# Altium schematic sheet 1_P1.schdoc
size 429 x 307 mm; Symbol: Drawing-Symbol_A4; Device: Drawing-Symbol_A4; Company: 嘉立创EDA; Version: V1.0; Page Size: A4; @Project Name: Dual_Motor_Driver_V3.1; @Page Count: 1; @Update Date: 2025-08-31; @Create Date: 2025-08-30; @Schematic Name: Schematic1; @Page No: 1; @Page Name: P1; @Create Time: 14:29:45; @Update Time: 22:24:23; Width: 1655; Height: 1170; Region Start: 1; X Region Count: 6; Y Region Count: 4; Blade Width: 10; Title Block Position: 3; @Board Name: PCB2
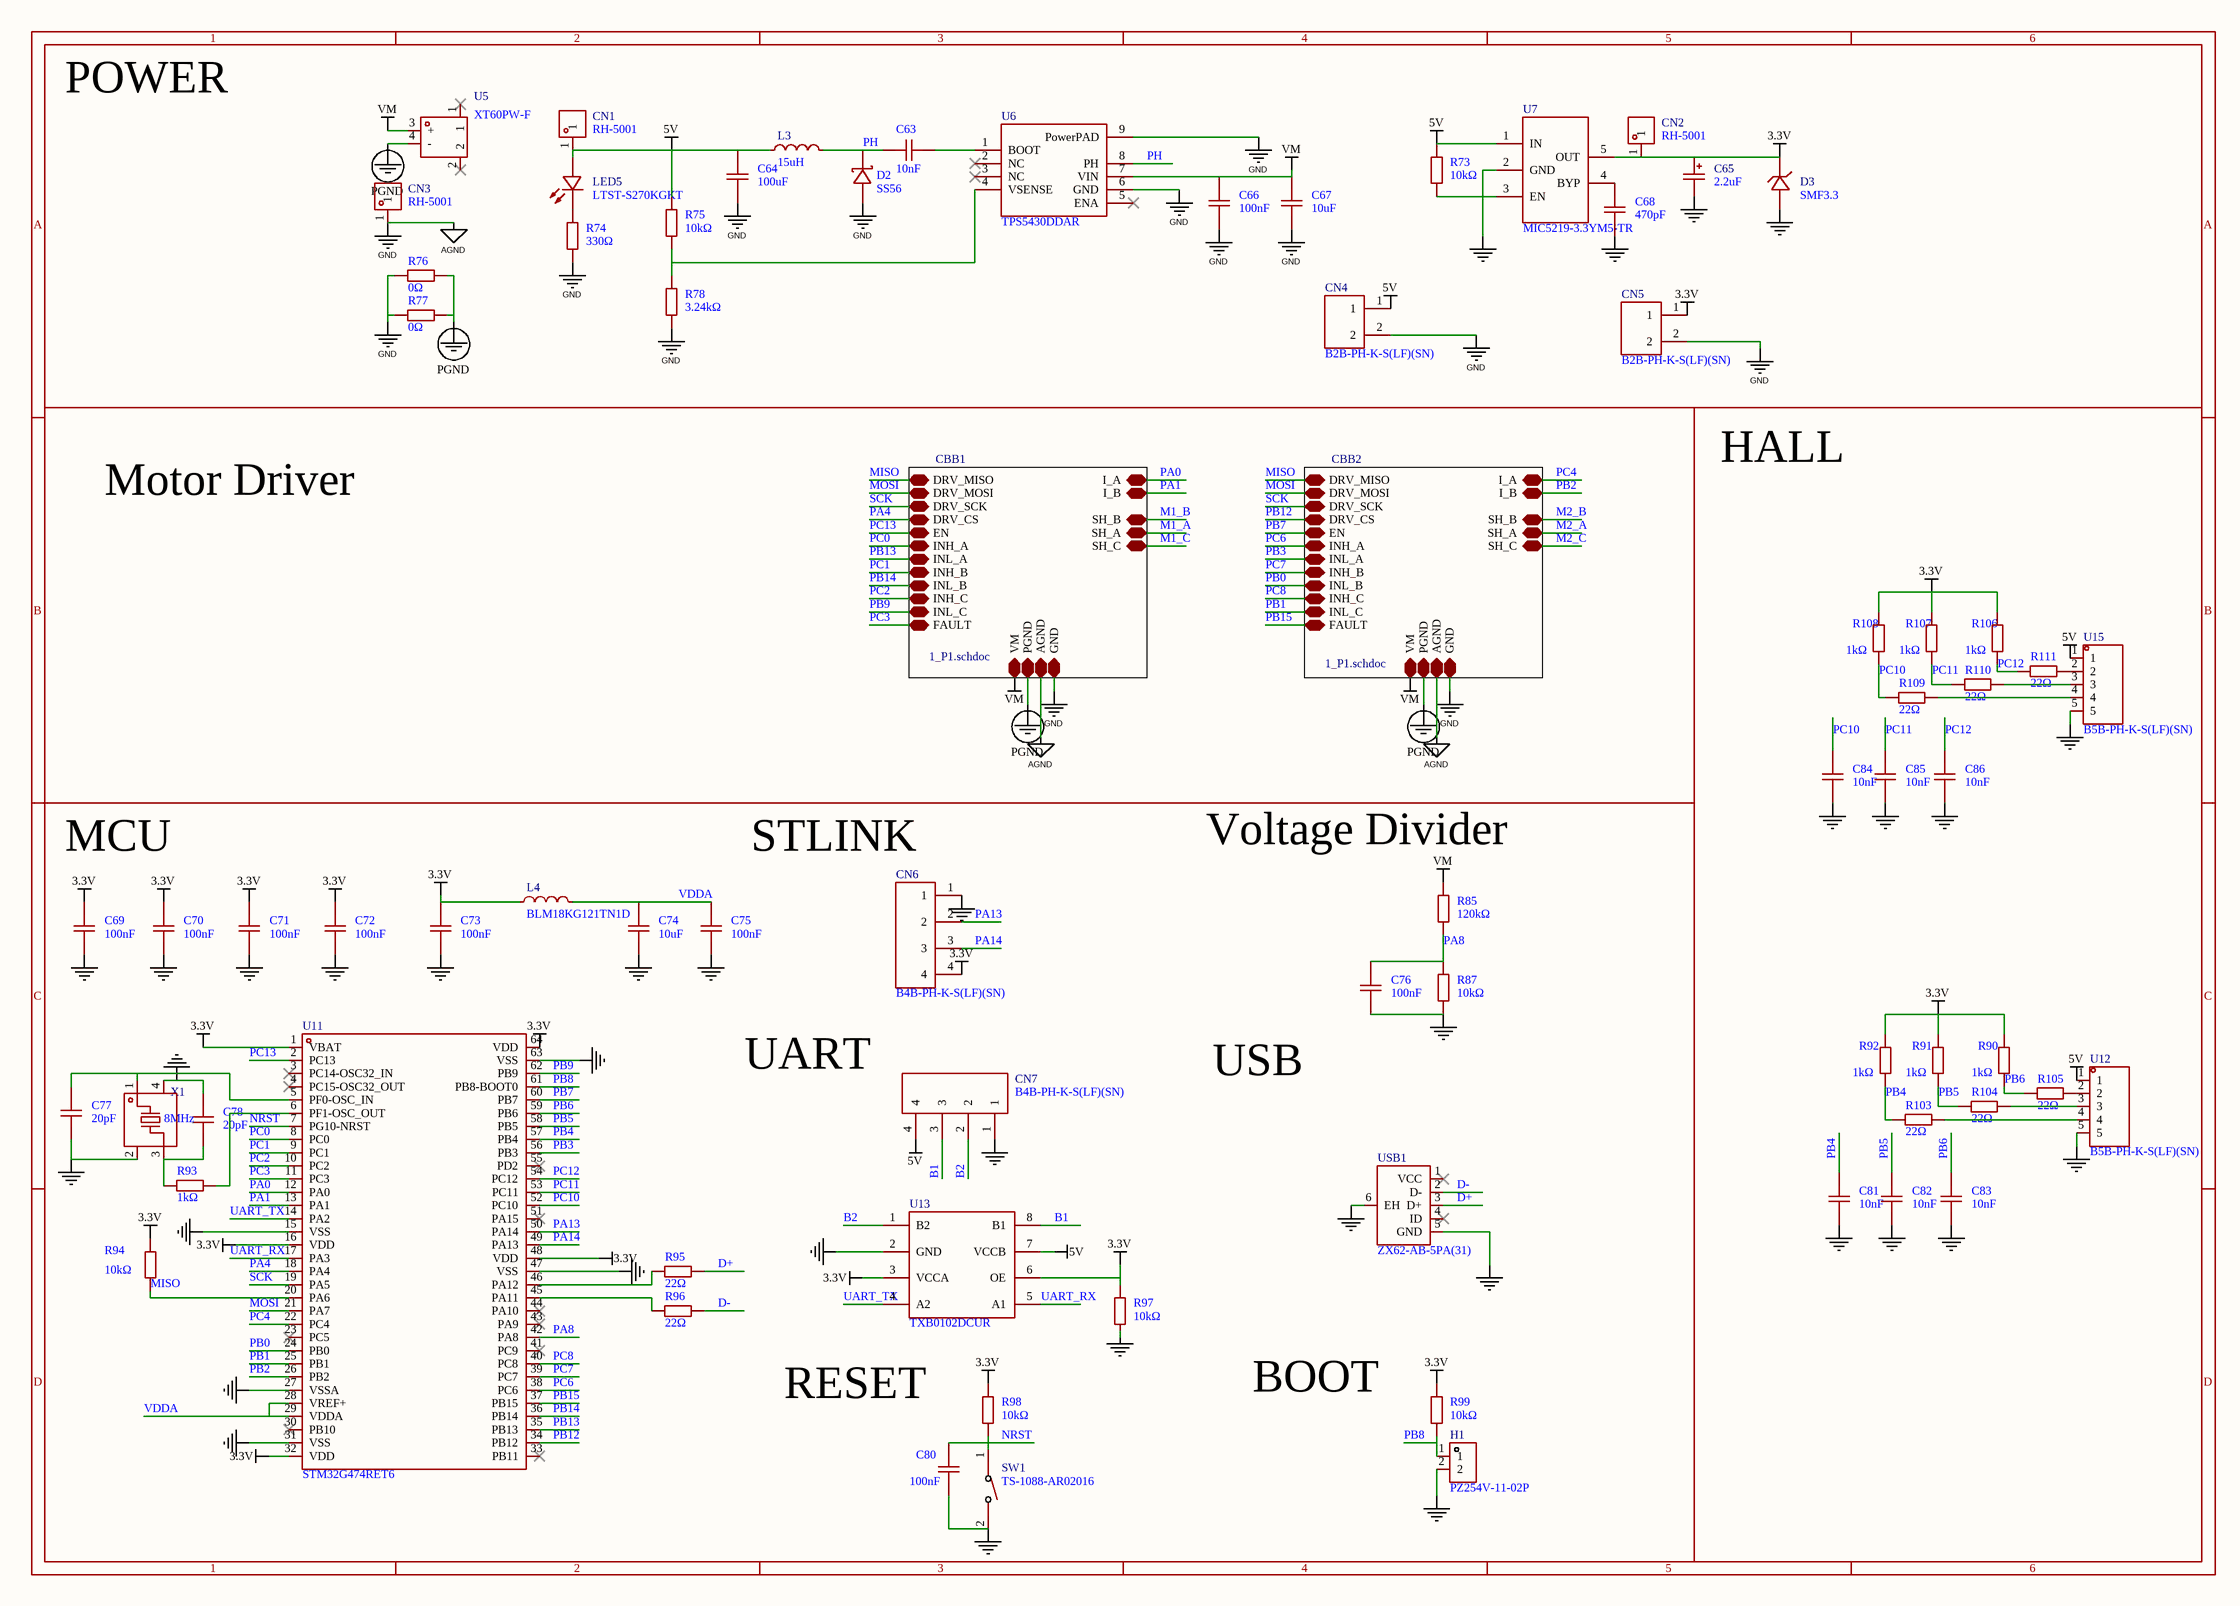
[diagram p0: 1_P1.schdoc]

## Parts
C63  10nF  [C0603]
C64  100uF  [CAP-SMD_BD6.3-L6.6-W6.6-LS7.2-R-RD]
C65  2.2uF  [CASE-A_3216]
C66  100nF  [C0603]
C67  10uF  [CAP-SMD_BD5.0-L5.3-W5.3-LS6.0-FD]
C68  470pF  [C0603]
C69  100nF  [C0603]
C70  100nF  [C0603]
C71  100nF  [C0603]
C72  100nF  [C0603]
C73  100nF  [C0603]
C74  10uF  [C0603]
C75  100nF  [C0603]
C76  100nF  [C1206]
C77  20pF  [C0603]
C78  20pF  [C0603]
C80  100nF  [C0603]
C81  10nF  [C0603]
C82  10nF  [C0603]
C83  10nF  [C0603]
C84  10nF  [C0603]
C85  10nF  [C0603]
C86  10nF  [C0603]
CN1  RH-5001  [TEST-TH_BD2.54-P1.4_BLACK]
CN2  RH-5001  [TEST-TH_BD2.54-P1.4_BLACK]
CN3  RH-5001  [TEST-TH_BD2.54-P1.4_BLACK]
CN4  B2B-PH-K-S(LF)(SN)  [CONN-TH_B2B-PH-K-S]
CN5  B2B-PH-K-S(LF)(SN)  [CONN-TH_B2B-PH-K-S]
CN6  B4B-PH-K-S(LF)(SN)  [CONN-TH_B4B-PH-K-S]
CN7  B4B-PH-K-S(LF)(SN)  [CONN-TH_B4B-PH-K-S]
D2  SS56  [SMA_L4.3-W2.6-LS5.2-RD]
D3  SMF3.3  [SOD-123FL_L3.0-W1.9-LS3.7-FD]
H1  PZ254V-11-02P  [HDR-TH_2P-P2.54-V-M]
L3  15uH  [IND-SMD_L10.8-W10.0_SLO1040H]
L4  BLM18KG121TN1D  [L0603]
LED5  LTST-S270KGKT  [LED-SMD_L1.7-W0.6-RD]
R73  10kΩ  [R0603]
R74  330Ω  [R0603]
R75  10kΩ  [R0603]
R76  0Ω  [R0603]
R77  0Ω  [R0603]
R78  3.24kΩ  [R0603]
R85  120kΩ  [R1206]
R87  10kΩ  [R1206]
R90  1kΩ  [R0603]
R91  1kΩ  [R0603]
R92  1kΩ  [R0603]
R93  1kΩ  [R0603]
R94  10kΩ  [R0603]
R95  22Ω  [R0603]
R96  22Ω  [R0603]
R97  10kΩ  [R0603]
R98  10kΩ  [R0603]
R99  10kΩ  [R0603]
R103  22Ω  [R0603]
R104  22Ω  [R0603]
R105  22Ω  [R0603]
R106  1kΩ  [R0603]
R107  1kΩ  [R0603]
R108  1kΩ  [R0603]
R109  22Ω  [R0603]
R110  22Ω  [R0603]
R111  22Ω  [R0603]
SW1  TS-1088-AR02016  [SW-SMD_L3.9-W3.0-P4.45]
U5  XT60PW-F  [TH_2P-XT60PW-F]
U6  TPS5430DDAR  [ESOP-8_L4.9-W3.9-P1.27-LS6.0-TL-EP]
U7  MIC5219-3.3YM5-TR  [SOT-23-5_L3.0-W1.7-P0.95-LS2.8-TL]
U11  STM32G474RET6  [LQFP-64_L10.0-W10.0-P0.50-LS12.0-BL]
U12  B5B-PH-K-S(LF)(SN)  [CONN-TH_B5B-PH-K-S-LF-SN]
U13  TXB0102DCUR  [VSSOP-8_L2.4-W2.1-P0.50-LS3.2-BR]
U15  B5B-PH-K-S(LF)(SN)  [CONN-TH_B5B-PH-K-S-LF-SN]
USB1  ZX62-AB-5PA(31)  [MICRO-USB-SMD_ZX62-AB-5PA]
X1  8MHz  [CRYSTAL-SMD_4P-L3.2-W2.5-BL]

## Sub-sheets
CBB1 = 1_P1.schdoc: DRV_MISO, DRV_MOSI, DRV_SCK, DRV_CS, EN, INH_A, INL_A, INH_B, INL_B, INH_C, INL_C, FAULT, I_A, I_B, SH_B, SH_A, SH_C, VM, PGND, AGND, GND  | Symbol: Motor_Driver; Device: Motor_Driver; Relevance: []
CBB2 = 1_P1.schdoc: DRV_MISO, DRV_MOSI, DRV_SCK, DRV_CS, EN, INH_A, INL_A, INH_B, INL_B, INH_C, INL_C, FAULT, I_A, I_B, SH_B, SH_A, SH_C, VM, PGND, AGND, GND  | Symbol: Motor_Driver; Device: Motor_Driver; Relevance: []

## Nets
3.3V: C65.1 C69.2 C70.2 C71.2 C72.2 C73.2 CN2.1 CN5.1 CN6.4 D3.1 L4.1 R90.2 R91.2 R92.2 R94.2 R97.2 R98.2 R99.2 R106.2 R107.2 R108.2 U7.5(OUT) U11.1(VBAT) U11.16(VDD) U11.32(VDD) U11.48(VDD) U11.64(VDD) U13.3(VCCA) U13.6(OE)
5V: C64.1 CN1.1 CN4.1 CN7.4 L3.1 LED5.2(A) R73.2 R75.2 U7.1(IN) U12.1 U13.7(VCCB) U15.1
AGND: C64.2 C65.2 C66.1 C67.2 C68.1 C69.1 C70.1 C71.1 C72.1 C73.1 C74.1 C75.1 C76.1 C77.2 C78.2 C80.1 C81.1 C82.1 C83.1 C84.1 C85.1 C86.1 CN3.1 CN4.2 CN5.2 CN6.1 CN7.1 D2.2(A) D3.2 H1.2 R74.1 R76.1 R77.1 R78.1 R87.1 R97.1 SW1.2 U6.6(GND) U6.9(PowerPAD) U7.2(GND) U11.15(VSS) U11.27(VSSA) U11.31(VSS) U11.47(VSS) U11.63(VSS) U12.5 U13.2(GND) U15.5 USB1.5(GND) USB1.6(EH) X1.2(GND) X1.4(GND) ; sheet CBB1/AGND, sheet CBB1/GND, sheet CBB2/AGND, sheet CBB2/GND  [also labelled GND]
PGND: R76.2 R77.2 U5.4(-) ; sheet CBB1/PGND, sheet CBB2/PGND
VM: C66.2 C67.1 R85.2 U5.3(+) U6.7(VIN) ; sheet CBB1/VM, sheet CBB2/VM
B1: CN7.3 U13.8(B1)
B2: CN7.2 U13.1(B2)
D+: R95.2 USB1.3(D+)
D-: R96.2 USB1.2(D-)
MISO: R94.1 U11.20(PA6) ; sheet CBB1/DRV_MISO, sheet CBB2/DRV_MISO
MOSI: U11.21(PA7) ; sheet CBB1/DRV_MOSI, sheet CBB2/DRV_MOSI
NRST: C80.2 R98.1 SW1.1 U11.7(PG10-NRST)
PA0: U11.12(PA0) ; sheet CBB1/I_A
PA1: U11.13(PA1) ; sheet CBB1/I_B
PA4: U11.18(PA4) ; sheet CBB1/DRV_CS
PA8: C76.2 R85.1 R87.2 U11.42(PA8)
PA13: CN6.2 U11.50(PA14)
PA14: CN6.3 U11.49(PA13)
PB0: U11.24(PB0) ; sheet CBB2/INL_B
PB1: U11.25(PB1) ; sheet CBB2/INL_C
PB2: U11.26(PB2) ; sheet CBB2/I_B
PB3: U11.56(PB3) ; sheet CBB2/INL_A
PB4: C81.2 R92.1 R103.1 U11.57(PB4)
PB5: C82.2 R91.1 R104.1 U11.58(PB5)
PB6: C83.2 R90.1 R105.1 U11.59(PB6)
PB7: U11.60(PB7) ; sheet CBB2/EN
PB8: H1.1 R99.1 U11.61(PB8-BOOT0)
PB9: U11.62(PB9) ; sheet CBB1/INL_C
PB12: U11.34(PB12) ; sheet CBB2/DRV_CS
PB13: U11.35(PB13) ; sheet CBB1/INL_A
PB14: U11.36(PB14) ; sheet CBB1/INL_B
PB15: U11.37(PB15) ; sheet CBB2/FAULT
PC0: U11.8(PC0) ; sheet CBB1/INH_A
PC1: U11.9(PC1) ; sheet CBB1/INH_B
PC2: U11.10(PC2) ; sheet CBB1/INH_C
PC3: U11.11(PC3) ; sheet CBB1/FAULT
PC4: U11.22(PC4) ; sheet CBB2/I_A
PC6: U11.38(PC6) ; sheet CBB2/INH_A
PC7: U11.39(PC7) ; sheet CBB2/INH_B
PC8: U11.40(PC8) ; sheet CBB2/INH_C
PC10: C84.2 R108.1 R109.1 U11.52(PC10)
PC11: C85.2 R107.1 R110.1 U11.53(PC11)
PC12: C86.2 R106.1 R111.1 U11.54(PC12)
PC13: U11.2(PC13) ; sheet CBB1/EN
PH: C63.1 D2.1(K) L3.2 U6.8(PH)
SCK: U11.19(PA5) ; sheet CBB1/DRV_SCK, sheet CBB2/DRV_SCK
UART_RX: U11.17(PA3) U13.5(A1)
UART_TX: U11.14(PA2) U13.4(A2)
VDDA: C74.2 C75.2 L4.2 U11.28(VREF+) U11.29(VDDA)
NetC63_2: C63.2 U6.1(BOOT)
NetC68_2: C68.2 U7.4(BYP)
NetC77_1: C77.1 U11.5(PF0-OSC_IN) X1.1
NetC78_1: C78.1 R93.1 X1.3
NetLED5_1: LED5.1(K) R74.2
NetR73_1: R73.1 U7.3(EN)
NetR75_1: R75.1 R78.2 U6.4(VSENSE)
NetR93_2: R93.2 U11.6(PF1-OSC_OUT)
NetR95_1: R95.1 U11.46(PA12)
NetR96_1: R96.1 U11.45(PA11)
NetR103_2: R103.2 U12.4
NetR104_2: R104.2 U12.3
NetR105_2: R105.2 U12.2
NetR109_2: R109.2 U15.4
NetR110_2: R110.2 U15.3
NetR111_2: R111.2 U15.2

Not connected (* = marked no-connect by the designer): U5 1* 2*; U6 2(NC)* 3(NC)* 5(ENA)*; U11 3(PC14-OSC32_IN)* 4(PC15-OSC32_OUT)* 23(PC5)* 30(PB10)* 33(PB11)* 41(PC9)* 43(PA9)* 44(PA10)* 51(PA15)* 55(PD2)*; USB1 1(VCC)* 4(ID)*

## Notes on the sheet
- POWER
- Motor Driver
- HALL
- MCU
- STLINK
- (near R85) Voltage Divider
- UART
- USB
- RESET
- BOOT

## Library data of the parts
C63 = CC0603KRX7R9BB103: Manufacturer: YAGEO(国巨); Symbol: Capacitance; Add into BOM: yes; Tolerance: ±10%; Voltage Rated: 50V; Temperature Coefficient: X7R
C64 = VZH101M1ETR-0607: Manufacturer: lelon(立隆); Symbol: Capacitance; Add into BOM: yes; Tolerance: ±20%; Rated Voltage: 25V; φD: 6.3mm; L: 7.7mm; Lifetime @ Temp: 2000hrs@105℃; Check: false
C65 = TAJA225K016RNJ: Manufacturer: Kyocera AVX; Add into BOM: yes; Tolerance: ±10%; Rated Voltage: 16V; Equivalent Series Resistance(ESR): 6.5Ω@100kHz
C66 C69-C73 C75 C80 = CC0603KRX7R9BB104: Manufacturer: YAGEO(国巨); Symbol: Capacitance; Add into BOM: yes; Tolerance: ±10%; Voltage Rating: 50V; Temperature Coefficient: X7R
C67 = JVJ50v10M5x5: Manufacturer: 捷而瑞; Symbol: Capacitance; Add into BOM: yes; Tolerance: ±20%; Voltage Rating: 50V; Ripple Current: 18mA@120Hz
C68 = CC0603JRNPO9BN471: Manufacturer: YAGEO(国巨); Symbol: Capacitance; Add into BOM: yes; Tolerance: ±5%; Voltage Rated: 50V; Temperature Coefficient: NP0
C74 = CL10A106KP8NNNC: Manufacturer: SAMSUNG(三星); Symbol: Capacitance; Add into BOM: yes; Tolerance: ±10%; Voltage Rated: 10V; Temperature Coefficient: X5R
C76 = GRM31C5C1H104JA01L: Manufacturer: muRata(村田); Symbol: Capacitance; Add into BOM: yes; Tolerance: ±5%; Voltage Rated: 50V; Temperature Coefficient: C0G
C77 C78 = CC0603FRNPO9BN200: Manufacturer: YAGEO(国巨); Symbol: Capacitance; Add into BOM: yes; Tolerance: ±1%; Voltage Rated: 50V; Temperature Coefficient: NP0
C81-C86 = CAP_0603: Symbol: Capacitance; Convert to PCB: yes
CN1-CN3 = RH-5001: Manufacturer: 荣和; Add into BOM: yes; Connector Type: 插针型(穿板); Plastic Color: 黑色; Board Space (Diameter φ/ Length x Width): 2.5mm
CN4 CN5 = B2B-PH-K-S(LF)(SN): Manufacturer: JST; Add into BOM: yes; Pins Structure: 1x2P; Pitch: 2mm; Reference Series: PH; Number of PINs Per Row: 2; Current Rating: 2A; Voltage Rating: 100V; Plastic Material: PA66; Flame Retardant Rating: UL94V-0; Supplementary Features: 打K脚; Z-Height of the Board: 6mm; X-Length of Bottom Edge on Board (Spacing Line): 5.9mm; Y-Width of Bottom Edge on Board: 4.5mm
CN6 CN7 = B4B-PH-K-S(LF)(SN): Manufacturer: JST; Add into BOM: yes; Pins Structure: 1x4P; Pitch: 2mm; Reference Series: PH; Number of PINs Per Row: 4; Current Rating (Max): 2A; Rated Voltage (Max): 100V; Plastic Material: PA66; Flame Retardant Rating: UL94V-0; Supplementary Features: 打K脚; Z-Height of the Board: 6mm; X-Length of Bottom Edge on Board (Spacing Line): 9.9mm; Y-Width of Bottom Edge on Board: 4.5mm
D2 = SS56_C65009: Manufacturer: MDD(辰达半导体); Add into BOM: yes; Diode Configuration: 独立式; Forward Voltage (Vf@If): 700mV@5A; Reverse Voltage (Vr): 60V; Rectified Current: 5A; Reverse Leakage Current (Ir): 1mA@60V
D3 = SMF3.3: Manufacturer: Littelfuse(美国力特); Symbol: SMF5.0A_C151296; Add into BOM: yes; Reverse Stand-Off Voltage (Vrwm): 3.3V; Maximum Clamping Voltage: 6.8V; Peak Pulse Current (Ipp)@10/1000us: 30A; Peak Pulse Power Dissipation (Ppp)@10/1000us: 200W; Breakdown Voltage: 3.4V; Type: TVS
H1 = PZ254V-11-02P: Manufacturer: XFCN(兴飞); Add into BOM: yes; Pin Structure: 1x2P; Pitch: 2.54mm; Circluar Pins/Square Pins: 方针
L3 = SLO1040H150MTT: Manufacturer: Sunltech(韩国顺磁); Add into BOM: yes; Tolerance: ±20%; Rated Current: 4.5A; DC Resistance (DCR): 45mΩ; Check: false
L4 = BLM18KG121TN1D: Manufacturer: muRata(村田); Add into BOM: yes; Impedance @ Frequency: 120Ω@100MHz; Tolerance: ±25%; DC Resistance: 30mΩ; Current Rating: 3A; Circuits: 1
LED5 = LTST-S270KGKT: Manufacturer: LITEON(光宝); Add into BOM: yes; Emitted Color: 黄绿色; Power Dissipation: 75mW; Forward Current: 20mA; Dominant Wavelength: 571nm; Peak Wavelength: 574nm; Lens Color: 无色透明透镜; Viewing Angle: 130°; Mounting Sytle: 侧贴
R73 R75 R94 R97-R99 = 0603WAF1002T5E: Manufacturer: UNI-ROYAL(厚声); Symbol: 电阻; Add into BOM: yes; Tolerance: ±1%; Power(Watts): 100mW; Overload Voltage (Max): 75V; Temperature Coefficient: ±100ppm/℃
R74 = 0603WAF3300T5E: Manufacturer: UNI-ROYAL(厚声); Symbol: 电阻; Add into BOM: yes; Tolerance: ±1%; Power(Watts): 100mW; Overload Voltage (Max): 75V; Temperature Coefficient: ±100ppm/℃
R76 R77 = RC0603FR-070RL: Manufacturer: YAGEO(国巨); Symbol: 电阻; Add into BOM: yes; Tolerance: ±1%; Power(Watts): 100mW; Overload Voltage (Max): 75V
R78 = 0603WAF3241T5E: Manufacturer: UNI-ROYAL(厚声); Symbol: 电阻; Add into BOM: yes; Tolerance: ±1%; Power(Watts): 100mW; Overload Voltage (Max): 75V; Temperature Coefficient: ±100ppm/℃
R85 = 1206W4F1203T5E: Manufacturer: UNI-ROYAL(厚声); Symbol: 电阻; Add into BOM: yes; Tolerance: ±1%; Power(Watts): 250mW; Overload Voltage (Max): 200V; Temperature Coefficient: ±100ppm/℃
R87 = 1206W4F1002T5E: Manufacturer: UNI-ROYAL(厚声); Symbol: 电阻; Add into BOM: yes; Tolerance: ±1%; Power(Watts): 250mW; Overload Voltage (Max): 200V; Temperature Coefficient: ±100ppm/℃
R90-R92 R106-R108 = 0603WAF1002T5E: Manufacturer: UNI-ROYAL(厚声); Symbol: 电阻; Add into BOM: yes; Tolerance: ±1%; Power(Watts): 100mW; Temperature Coefficient: ±100ppm/℃; Overload Voltage (Max): 75V
R93 = 0603WAF1001T5E: Manufacturer: UNI-ROYAL(厚声); Symbol: 电阻; Add into BOM: yes; Tolerance: ±1%; Power(Watts): 100mW; Overload Voltage (Max): 75V; Temperature Coefficient: ±100ppm/℃
R95 R96 = 0603WAF220JT5E: Manufacturer: UNI-ROYAL(厚声); Symbol: 电阻; Add into BOM: yes; Tolerance: ±1%; Power(Watts): 100mW; Overload Voltage (Max): 75V; Temperature Coefficient: ±100ppm/℃
R103-R105 R109-R111 = Res_0603: Symbol: 电阻; Convert to PCB: yes
SW1 = TS-1088-AR02016: Manufacturer: XUNPU(讯普); Add into BOM: yes; Circuit: 单刀单掷; Actuator Style: 圆形按钮; Operating Force: 160gf; Switch Length: 4mm; Switch Width: 3mm; Switch Height: 2mm; Strike Gundam: 不带; Contact Current: 50mA; Voltage Rating (DC): 12V; Insulation Resistance: 100MΩ; Actuator/Cap Color: 黑色; Pin Style: SMD接片; Mechanical Life: 10万次
U5 = XT60PW-F: Manufacturer: AMASS(艾迈斯); Symbol: XT60PW-F_C428722; Add into BOM: yes; InterfaceType: 母头
U6 = TPS5430DDAR: Manufacturer: TI(德州仪器); Add into BOM: yes; Function: 降压型; Output Type: 可调; Input Voltage: 5.5V~36V; Output Voltage: 1.221V~32.04V; Output Current: 3A; Switching Frequency: 500kHz; Synchronous Rectification: 否; Number of Outputs: 1; Topology: 降压式; Switch tube (built-in/external): 内置
U7 = MIC5219-3.3YM5-TR: Manufacturer: MICROCHIP(美国微芯); Add into BOM: yes; Output Type: 固定; Maximum Input Voltage: 12V; Output Voltage: 3.3V; Output Current: 500mA; Power Supply Rejection Ratio (PSRR): 75dB@(120Hz); Dropout Voltage: 600mV@(500mA); standby current: 8uA; Output Polarity: 正极; Number of Outputs: 1
U11 = STM32G474RET6: Manufacturer: ST(意法半导体); Add into BOM: yes; CPU Core: ARM-M4; CPU Maximum Speed: 170MHz; Program Storage Size: 512KB; Program Memory Type: FLASH; Number of I/O: 52; ADC (Bit): 12bit; Voltage - Supply: 1.71V~3.6V
U12 U15 = B5B-PH-K-S(LF)(SN): Manufacturer: JST; Symbol: B5B-PH-K-S-(LF)(SN); Add into BOM: yes; Pins Structure: 1x5P; Pitch: 2mm; Reference Series: PH; Number of PINs Per Row: 5; Current Rating (Max): 2A; Rated Voltage (Max): 100V; Plastic Material: PA66; Flame Retardant Rating: UL94V-0; Supplementary Features: 打K脚; Z-Height of the Board: 6mm; X-Length of Bottom Edge on Board (Spacing Line): 11.9mm; Y-Width of Bottom Edge on Board: 4.5mm
U13 = TXB0102DCUR: Manufacturer: TI(德州仪器); Add into BOM: yes; Channel Type: 双向; Data Rate: 100Mbps; Voltage - Supply(VCCA): 1.2V~3.6V; Voltage - Supply(VCCB): 1.65V~5.5V; Number of Circuits: 2; Output Type: 三态
USB1 = ZX62-AB-5PA(31): Manufacturer: HRS(广濑); Add into BOM: yes; Connector Type: Micro-AB; Gender: 母; Number of Ports: 1; Number of Contacts: 5P
X1 = X32258MSB4SI: Manufacturer: YXC(扬兴晶振); Add into BOM: yes; Normal temperature Frequency Tolerance: ±10ppm; Load Capacitance: 20pF; Frequency Stability: ±20ppm; Equivalent Series Resistance(ESR): 120Ω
